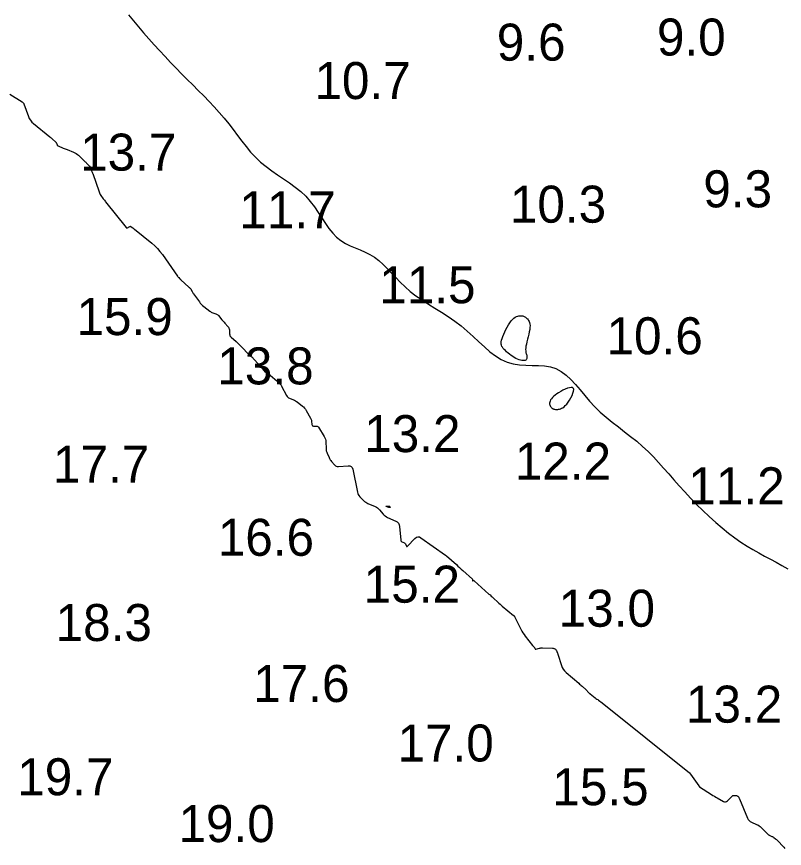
# Model space of a CAD drawing. Extents: x 3040093 to 3056816, y 408076 to 509144.
# Drawn here: x 3044186.9 to 3044290.6, y 435756.3 to 435868.7 of the extents above; entities that cross this region are included whole.
import ezdxf

# ---------------------------------------------------------------- set-up
doc = ezdxf.new("R2010")
doc.units = 0
for name, color, linetype in [('V-CHAN-CONT-EL12-1112', 7, 'Continuous'), ('V-CHAN-CONT-EL15', 7, 'Continuous'), ('V-TOPO-SOUN-0810', 7, 'Continuous')]:
    doc.layers.add(name, color=color, linetype=linetype)

msp = doc.modelspace()

# ---------------------------------------------------------------- linework, layer by layer
at = {"layer": 'V-CHAN-CONT-EL12-1112'}
msp.add_lwpolyline([(3044202, 435868.95), (3044202.67, 435868.14), (3044203.35, 435867.33), (3044204.04, 435866.52), (3044204.75, 435865.71), (3044205.47, 435864.91), (3044206.19, 435864.11), (3044206.93, 435863.32), (3044207.67, 435862.53), (3044208.42, 435861.76), (3044209.17, 435860.99), (3044209.93, 435860.23), (3044210.68, 435859.49), (3044211.43, 435858.74), (3044212.17, 435858), (3044212.89, 435857.26), (3044213.59, 435856.52), (3044214.27, 435855.76), (3044214.92, 435855), (3044215.54, 435854.22), (3044216.13, 435853.44), (3044216.72, 435852.66), (3044217.3, 435851.89), (3044217.89, 435851.14), (3044218.5, 435850.41), (3044219.15, 435849.71), (3044219.84, 435849.06), (3044220.58, 435848.45), (3044221.35, 435847.88), (3044222.15, 435847.33), (3044222.96, 435846.79), (3044223.76, 435846.25), (3044224.54, 435845.68), (3044225.27, 435845.09), (3044225.95, 435844.44), (3044226.56, 435843.75), (3044227.12, 435843.01), (3044227.64, 435842.26), (3044228.13, 435841.51), (3044228.61, 435840.78), (3044229.09, 435840.09), (3044229.59, 435839.46), (3044230.12, 435838.9), (3044230.7, 435838.45), (3044231.32, 435838.07), (3044231.96, 435837.75), (3044232.62, 435837.46), (3044233.29, 435837.18), (3044233.96, 435836.89), (3044234.6, 435836.57), (3044235.23, 435836.19), (3044235.83, 435835.74), (3044236.4, 435835.23), (3044236.96, 435834.67), (3044237.52, 435834.07), (3044238.1, 435833.45), (3044238.71, 435832.82), (3044239.37, 435832.19), (3044240.07, 435831.58), (3044240.84, 435830.99), (3044241.66, 435830.43), (3044242.52, 435829.88), (3044243.4, 435829.33), (3044244.3, 435828.77), (3044245.2, 435828.18), (3044246.09, 435827.57), (3044246.95, 435826.92), (3044247.77, 435826.23), (3044248.56, 435825.51), (3044249.33, 435824.79), (3044250.09, 435824.09), (3044250.84, 435823.44), (3044251.6, 435822.86), (3044252.37, 435822.38), (3044253.16, 435822.02), (3044253.99, 435821.78), (3044254.83, 435821.66), (3044255.68, 435821.61), (3044256.54, 435821.59), (3044257.38, 435821.57), (3044258.21, 435821.51), (3044259, 435821.38), (3044259.75, 435821.15), (3044260.46, 435820.77), (3044261.12, 435820.27), (3044261.76, 435819.67), (3044262.38, 435819), (3044263.01, 435818.27), (3044263.65, 435817.52), (3044264.31, 435816.75), (3044265.01, 435816), (3044265.75, 435815.28), (3044266.54, 435814.59), (3044267.35, 435813.92), (3044268.19, 435813.27), (3044269.02, 435812.63), (3044269.85, 435811.98), (3044270.67, 435811.33), (3044271.45, 435810.65), (3044272.2, 435809.95), (3044272.92, 435809.23), (3044273.62, 435808.49), (3044274.31, 435807.72), (3044274.99, 435806.94), (3044275.69, 435806.14), (3044276.41, 435805.33), (3044277.16, 435804.5), (3044277.95, 435803.66), (3044278.77, 435802.81), (3044279.61, 435801.98), (3044280.47, 435801.16), (3044281.34, 435800.37), (3044282.21, 435799.62), (3044283.08, 435798.92), (3044283.93, 435798.28), (3044284.76, 435797.7), (3044285.58, 435797.17), (3044286.38, 435796.7), (3044287.17, 435796.25), (3044287.96, 435795.83), (3044288.73, 435795.42), (3044289.51, 435795), (3044290.29, 435794.57), (3044291.08, 435794.11)], dxfattribs=at)
for points in [[(3044252.52, 435824.03), (3044252.44, 435824.16), (3044252.38, 435824.3), (3044252.35, 435824.44), (3044252.34, 435824.59), (3044252.37, 435824.77), (3044252.41, 435824.98), (3044252.48, 435825.21), (3044252.58, 435825.49), (3044252.7, 435825.79), (3044252.84, 435826.11), (3044253, 435826.44), (3044253.16, 435826.76), (3044253.34, 435827.07), (3044253.52, 435827.36), (3044253.71, 435827.61), (3044253.89, 435827.81), (3044254.08, 435827.97), (3044254.26, 435828.1), (3044254.43, 435828.19), (3044254.6, 435828.25), (3044254.76, 435828.28), (3044254.9, 435828.3), (3044255.04, 435828.3), (3044255.16, 435828.29), (3044255.27, 435828.27), (3044255.38, 435828.24), (3044255.47, 435828.2), (3044255.56, 435828.15), (3044255.64, 435828.09), (3044255.73, 435828.02), (3044255.81, 435827.94), (3044255.9, 435827.86), (3044255.99, 435827.76), (3044256.07, 435827.65), (3044256.14, 435827.52), (3044256.2, 435827.37), (3044256.24, 435827.18), (3044256.26, 435826.97), (3044256.25, 435826.72), (3044256.22, 435826.44), (3044256.16, 435826.12), (3044256.08, 435825.79), (3044256, 435825.45), (3044255.91, 435825.11), (3044255.83, 435824.78), (3044255.76, 435824.47), (3044255.7, 435824.19), (3044255.67, 435823.95), (3044255.66, 435823.74), (3044255.67, 435823.57), (3044255.69, 435823.42), (3044255.71, 435823.29), (3044255.75, 435823.18), (3044255.78, 435823.07), (3044255.81, 435822.96), (3044255.83, 435822.85), (3044255.84, 435822.74), (3044255.84, 435822.63), (3044255.83, 435822.53), (3044255.8, 435822.44), (3044255.75, 435822.36), (3044255.68, 435822.3), (3044255.58, 435822.25), (3044255.46, 435822.23), (3044255.31, 435822.23), (3044255.15, 435822.26), (3044254.97, 435822.3), (3044254.77, 435822.36), (3044254.56, 435822.44), (3044254.35, 435822.54), (3044254.13, 435822.66), (3044253.91, 435822.79), (3044253.7, 435822.93), (3044253.48, 435823.09), (3044253.28, 435823.25), (3044253.09, 435823.42), (3044252.92, 435823.58), (3044252.76, 435823.74), (3044252.63, 435823.89)], [(3044259.32, 435815.74), (3044259.41, 435815.7), (3044259.49, 435815.67), (3044259.58, 435815.66), (3044259.68, 435815.65), (3044259.78, 435815.64), (3044259.89, 435815.65), (3044260, 435815.65), (3044260.12, 435815.67), (3044260.25, 435815.69), (3044260.39, 435815.73), (3044260.53, 435815.79), (3044260.69, 435815.87), (3044260.85, 435815.99), (3044261.02, 435816.15), (3044261.21, 435816.36), (3044261.4, 435816.61), (3044261.6, 435816.9), (3044261.78, 435817.21), (3044261.94, 435817.52), (3044262.06, 435817.82), (3044262.14, 435818.09), (3044262.16, 435818.32), (3044262.12, 435818.48), (3044262, 435818.58), (3044261.81, 435818.6), (3044261.58, 435818.57), (3044261.3, 435818.49), (3044261, 435818.38), (3044260.7, 435818.23), (3044260.4, 435818.07), (3044260.11, 435817.9), (3044259.86, 435817.73), (3044259.63, 435817.56), (3044259.44, 435817.39), (3044259.28, 435817.23), (3044259.15, 435817.07), (3044259.04, 435816.92), (3044258.97, 435816.77), (3044258.92, 435816.62), (3044258.9, 435816.49), (3044258.9, 435816.36), (3044258.93, 435816.24), (3044258.97, 435816.13), (3044259.02, 435816.03), (3044259.09, 435815.94), (3044259.16, 435815.86), (3044259.24, 435815.79)]]:
    msp.add_lwpolyline(points, close=True, dxfattribs=at)
at = {"layer": 'V-CHAN-CONT-EL15'}
for points in [[(3044185.97, 435858.22), (3044187.62, 435857.2), (3044187.65, 435857.19), (3044187.67, 435857.17), (3044187.69, 435857.15), (3044187.71, 435857.12), (3044187.79, 435857.03), (3044187.81, 435857), (3044187.83, 435856.98), (3044187.84, 435856.95), (3044187.85, 435856.92), (3044188.47, 435855.23), (3044188.59, 435854.95), (3044188.75, 435854.7), (3044188.94, 435854.47), (3044189.17, 435854.26), (3044191.38, 435852.45), (3044191.47, 435852.38), (3044191.55, 435852.31), (3044191.64, 435852.23), (3044191.72, 435852.16), (3044192.13, 435851.81), (3044192.18, 435851.76), (3044192.21, 435851.72), (3044192.24, 435851.67), (3044192.27, 435851.62), (3044192.35, 435851.4), (3044192.38, 435851.34), (3044192.41, 435851.3), (3044192.46, 435851.27), (3044192.51, 435851.24), (3044193.17, 435850.95), (3044193.3, 435850.89), (3044193.43, 435850.84), (3044193.57, 435850.79), (3044193.7, 435850.74), (3044194.57, 435850.4), (3044194.76, 435850.31), (3044194.93, 435850.21), (3044195.1, 435850.1), (3044195.25, 435849.97), (3044196.16, 435849.1), (3044196.22, 435849.04), (3044196.27, 435848.98), (3044196.33, 435848.93), (3044196.39, 435848.87), (3044196.7, 435848.56), (3044196.71, 435848.54), (3044196.73, 435848.53), (3044196.75, 435848.51), (3044196.76, 435848.49), (3044196.83, 435848.42), (3044196.84, 435848.41), (3044196.85, 435848.39), (3044196.86, 435848.37), (3044196.87, 435848.35), (3044196.94, 435848.04), (3044196.95, 435847.99), (3044196.97, 435847.95), (3044196.99, 435847.9), (3044197.01, 435847.86), (3044197.09, 435847.68), (3044197.11, 435847.64), (3044197.13, 435847.59), (3044197.15, 435847.55), (3044197.17, 435847.5), (3044198.02, 435845.03), (3044198.07, 435844.91), (3044198.13, 435844.78), (3044198.19, 435844.67), (3044198.27, 435844.55), (3044198.58, 435844.11), (3044198.66, 435844), (3044198.74, 435843.89), (3044198.83, 435843.78), (3044198.91, 435843.67), (3044201.7, 435840.22), (3044201.7, 435840.21), (3044201.71, 435840.21), (3044201.72, 435840.19), (3044201.73, 435840.18), (3044201.73, 435840.18), (3044201.74, 435840.17), (3044201.74, 435840.17), (3044201.77, 435840.15), (3044201.77, 435840.15), (3044201.78, 435840.15), (3044201.79, 435840.15), (3044201.79, 435840.15), (3044202.17, 435840.35), (3044202.22, 435840.37), (3044202.28, 435840.38), (3044202.33, 435840.36), (3044202.38, 435840.33), (3044202.59, 435840.17), (3044202.64, 435840.13), (3044202.69, 435840.09), (3044202.74, 435840.05), (3044202.79, 435840.01), (3044205.14, 435838.08), (3044205.54, 435837.73), (3044205.91, 435837.36), (3044206.25, 435836.96), (3044206.57, 435836.55), (3044208.64, 435833.64), (3044208.65, 435833.62), (3044208.66, 435833.61), (3044208.67, 435833.59), (3044208.68, 435833.58), (3044208.73, 435833.5), (3044208.73, 435833.49), (3044208.73, 435833.49), (3044208.74, 435833.49), (3044208.74, 435833.48), (3044208.76, 435833.47), (3044208.77, 435833.47), (3044208.77, 435833.47), (3044208.78, 435833.46), (3044208.78, 435833.46), (3044208.95, 435833.28), (3044208.98, 435833.25), (3044209.01, 435833.22), (3044209.04, 435833.19), (3044209.07, 435833.16), (3044210.17, 435832.17), (3044210.24, 435832.1), (3044210.3, 435832.03), (3044210.36, 435831.96), (3044210.41, 435831.88), (3044210.6, 435831.56), (3044210.65, 435831.48), (3044210.7, 435831.4), (3044210.75, 435831.32), (3044210.8, 435831.24), (3044211.57, 435830.16), (3044211.7, 435829.99), (3044211.84, 435829.83), (3044212, 435829.69), (3044212.16, 435829.55), (3044213.01, 435828.91), (3044213.09, 435828.85), (3044213.19, 435828.79), (3044213.28, 435828.75), (3044213.38, 435828.71), (3044213.79, 435828.57), (3044213.89, 435828.53), (3044213.98, 435828.47), (3044214.07, 435828.41), (3044214.14, 435828.33), (3044214.63, 435827.74), (3044214.73, 435827.63), (3044214.82, 435827.52), (3044214.92, 435827.41), (3044215.02, 435827.3), (3044215.43, 435826.86), (3044215.51, 435826.76), (3044215.57, 435826.64), (3044215.61, 435826.52), (3044215.63, 435826.39), (3044215.65, 435825.85), (3044215.67, 435825.72), (3044215.71, 435825.6), (3044215.77, 435825.5), (3044215.86, 435825.4), (3044216.53, 435824.81), (3044216.67, 435824.68), (3044216.81, 435824.55), (3044216.95, 435824.42), (3044217.09, 435824.28), (3044218.43, 435822.9), (3044218.44, 435822.89), (3044218.46, 435822.87), (3044218.48, 435822.86), (3044218.5, 435822.84), (3044218.58, 435822.8), (3044218.6, 435822.78), (3044218.62, 435822.77), (3044218.64, 435822.75), (3044218.65, 435822.74), (3044220.18, 435821.02), (3044220.2, 435820.99), (3044220.23, 435820.96), (3044220.25, 435820.94), (3044220.28, 435820.91), (3044220.37, 435820.79), (3044220.39, 435820.76), (3044220.42, 435820.74), (3044220.45, 435820.72), (3044220.48, 435820.7), (3044220.89, 435820.45), (3044220.96, 435820.41), (3044221.04, 435820.35), (3044221.11, 435820.3), (3044221.18, 435820.24), (3044222.05, 435819.49), (3044222.11, 435819.44), (3044222.17, 435819.38), (3044222.23, 435819.33), (3044222.29, 435819.27), (3044222.51, 435819.03), (3044222.56, 435818.97), (3044222.61, 435818.9), (3044222.65, 435818.84), (3044222.69, 435818.77), (3044223.34, 435817.52), (3044223.42, 435817.4), (3044223.52, 435817.3), (3044223.63, 435817.21), (3044223.76, 435817.15), (3044224.3, 435816.94), (3044224.44, 435816.88), (3044224.57, 435816.81), (3044224.69, 435816.73), (3044224.81, 435816.65), (3044225.51, 435816.1), (3044225.66, 435815.97), (3044225.8, 435815.83), (3044225.92, 435815.67), (3044226.02, 435815.51), (3044226.59, 435814.48), (3044226.64, 435814.38), (3044226.68, 435814.28), (3044226.71, 435814.17), (3044226.73, 435814.06), (3044226.78, 435813.59), (3044226.8, 435813.51), (3044226.84, 435813.44), (3044226.91, 435813.41), (3044226.99, 435813.39), (3044227.39, 435813.39), (3044227.48, 435813.38), (3044227.56, 435813.35), (3044227.63, 435813.3), (3044227.69, 435813.22), (3044228.45, 435811.98), (3044228.55, 435811.81), (3044228.61, 435811.62), (3044228.66, 435811.43), (3044228.67, 435811.24), (3044228.69, 435810.35), (3044228.71, 435810.19), (3044228.73, 435810.03), (3044228.78, 435809.88), (3044228.84, 435809.73), (3044229.11, 435809.13), (3044229.18, 435808.99), (3044229.25, 435808.85), (3044229.34, 435808.73), (3044229.44, 435808.61), (3044229.85, 435808.14), (3044229.95, 435808.03), (3044230.08, 435807.97), (3044230.21, 435807.93), (3044230.36, 435807.93), (3044231.66, 435808.04), (3044231.9, 435808.03), (3044232.09, 435807.94), (3044232.22, 435807.79), (3044232.3, 435807.56), (3044232.92, 435804.47), (3044232.97, 435804.3), (3044233.04, 435804.14), (3044233.13, 435803.99), (3044233.25, 435803.85), (3044233.77, 435803.34), (3044233.9, 435803.22), (3044234.05, 435803.11), (3044234.2, 435803.02), (3044234.36, 435802.94), (3044235.32, 435802.52), (3044235.49, 435802.44), (3044235.65, 435802.34), (3044235.79, 435802.22), (3044235.92, 435802.09), (3044236.42, 435801.51), (3044236.55, 435801.37), (3044236.69, 435801.25), (3044236.85, 435801.15), (3044237.01, 435801.06), (3044238.1, 435800.56), (3044238.32, 435800.43), (3044238.48, 435800.26), (3044238.58, 435800.05), (3044238.63, 435799.81), (3044238.78, 435797.97), (3044238.8, 435797.9), (3044238.83, 435797.84), (3044238.87, 435797.8), (3044238.93, 435797.76), (3044239.21, 435797.65), (3044239.27, 435797.62), (3044239.33, 435797.58), (3044239.37, 435797.52), (3044239.41, 435797.46), (3044239.55, 435797.18), (3044239.58, 435797.13), (3044239.62, 435797.1), (3044239.67, 435797.11), (3044239.72, 435797.15), (3044240.71, 435798.22), (3044240.9, 435798.37), (3044241.09, 435798.43), (3044241.3, 435798.41), (3044241.51, 435798.3), (3044244.83, 435795.95), (3044244.84, 435795.94), (3044244.84, 435795.94), (3044244.85, 435795.93), (3044244.85, 435795.93), (3044244.86, 435795.91), (3044244.87, 435795.91), (3044244.87, 435795.9), (3044244.88, 435795.9), (3044244.88, 435795.9), (3044244.94, 435795.88), (3044244.95, 435795.87), (3044244.96, 435795.87), (3044244.97, 435795.86), (3044244.97, 435795.86), (3044246.3, 435794.68), (3044246.52, 435794.48), (3044246.74, 435794.28), (3044246.96, 435794.08), (3044247.18, 435793.88), (3044248.47, 435792.7), (3044248.48, 435792.69), (3044248.49, 435792.67), (3044248.49, 435792.65), (3044248.49, 435792.63), (3044248.46, 435792.54), (3044248.45, 435792.52), (3044248.46, 435792.51), (3044248.47, 435792.5), (3044248.49, 435792.5), (3044248.6, 435792.52), (3044248.63, 435792.53), (3044248.65, 435792.52), (3044248.68, 435792.51), (3044248.7, 435792.5), (3044250.7, 435790.7), (3044250.85, 435790.57), (3044251, 435790.43), (3044251.15, 435790.3), (3044251.3, 435790.16), (3044251.9, 435789.61), (3044252.05, 435789.48), (3044252.2, 435789.34), (3044252.35, 435789.21), (3044252.5, 435789.08), (3044254.04, 435787.82), (3044254.06, 435787.81), (3044254.07, 435787.79), (3044254.08, 435787.78), (3044254.09, 435787.77), (3044254.13, 435787.71), (3044254.14, 435787.7), (3044254.15, 435787.69), (3044254.15, 435787.67), (3044254.16, 435787.66), (3044255.02, 435785.94), (3044255.15, 435785.7), (3044255.3, 435785.47), (3044255.45, 435785.24), (3044255.61, 435785.01), (3044256.59, 435783.75), (3044256.61, 435783.73), (3044256.63, 435783.7), (3044256.65, 435783.68), (3044256.68, 435783.66), (3044256.76, 435783.57), (3044256.79, 435783.55), (3044256.81, 435783.52), (3044256.82, 435783.49), (3044256.84, 435783.47), (3044256.94, 435783.3), (3044256.96, 435783.27), (3044256.99, 435783.25), (3044257.02, 435783.24), (3044257.06, 435783.25), (3044257.54, 435783.38), (3044257.64, 435783.4), (3044257.73, 435783.41), (3044257.83, 435783.42), (3044257.92, 435783.42), (3044259.3, 435783.39), (3044259.35, 435783.39), (3044259.4, 435783.38), (3044259.45, 435783.36), (3044259.5, 435783.34), (3044259.68, 435783.23), (3044259.73, 435783.2), (3044259.76, 435783.17), (3044259.79, 435783.13), (3044259.82, 435783.08), (3044259.93, 435782.81), (3044259.95, 435782.75), (3044259.98, 435782.69), (3044260, 435782.63), (3044260.02, 435782.56), (3044260.5, 435781.04), (3044260.61, 435780.77), (3044260.74, 435780.53), (3044260.91, 435780.31), (3044261.12, 435780.11), (3044262.85, 435778.64), (3044262.96, 435778.54), (3044263.07, 435778.45), (3044263.18, 435778.35), (3044263.29, 435778.25), (3044263.83, 435777.74), (3044263.88, 435777.69), (3044263.92, 435777.65), (3044263.97, 435777.6), (3044264.01, 435777.55), (3044264.19, 435777.37), (3044264.24, 435777.32), (3044264.28, 435777.28), (3044264.33, 435777.24), (3044264.38, 435777.2), (3044265.04, 435776.69), (3044265.16, 435776.6), (3044265.28, 435776.51), (3044265.4, 435776.43), (3044265.52, 435776.34), (3044265.99, 435776), (3044277.8, 435766.52)], [(3044277.8, 435766.52), (3044277.92, 435766.36), (3044279.05, 435764.79), (3044279.05, 435764.78), (3044279.06, 435764.77), (3044279.07, 435764.77), (3044279.07, 435764.76), (3044279.11, 435764.73), (3044279.12, 435764.72), (3044279.13, 435764.71), (3044279.14, 435764.68), (3044279.15, 435764.68), (3044279.15, 435764.67), (3044279.16, 435764.67), (3044279.17, 435764.67), (3044280.78, 435763.62), (3044280.97, 435763.5), (3044281.16, 435763.39), (3044281.35, 435763.27), (3044281.54, 435763.16), (3044282.4, 435762.68), (3044282.55, 435762.62), (3044282.68, 435762.61), (3044282.81, 435762.66), (3044282.94, 435762.76), (3044283.57, 435763.4), (3044283.61, 435763.44), (3044283.66, 435763.47), (3044283.71, 435763.49), (3044283.77, 435763.49), (3044284.1, 435763.5), (3044284.12, 435763.5), (3044284.14, 435763.5), (3044284.15, 435763.49), (3044284.17, 435763.48), (3044284.24, 435763.43), (3044284.24, 435763.43), (3044284.25, 435763.42), (3044284.26, 435763.42), (3044284.27, 435763.41), (3044284.32, 435763.4), (3044284.33, 435763.39), (3044284.33, 435763.39), (3044284.34, 435763.38), (3044284.35, 435763.37), (3044284.42, 435763.3), (3044284.43, 435763.28), (3044284.45, 435763.26), (3044284.46, 435763.25), (3044284.46, 435763.23), (3044284.51, 435763.11), (3044284.52, 435763.09), (3044284.53, 435763.06), (3044284.54, 435763.04), (3044284.55, 435763.01), (3044285.66, 435760.4), (3044285.75, 435760.23), (3044285.86, 435760.09), (3044286, 435759.98), (3044286.17, 435759.89), (3044286.88, 435759.58), (3044287.05, 435759.5), (3044287.21, 435759.4), (3044287.37, 435759.29), (3044287.51, 435759.16), (3044288.44, 435758.23), (3044288.5, 435758.18), (3044288.55, 435758.14), (3044288.62, 435758.1), (3044288.68, 435758.07), (3044288.95, 435757.95), (3044289.01, 435757.92), (3044289.08, 435757.88), (3044289.14, 435757.84), (3044289.2, 435757.8), (3044289.43, 435757.63), (3044289.48, 435757.58), (3044289.54, 435757.54), (3044289.59, 435757.49), (3044289.64, 435757.44), (3044290.53, 435756.51), (3044290.69, 435756.34)]]:
    msp.add_lwpolyline(points, dxfattribs=at)
msp.add_lwpolyline([(3044237.36, 435802.4), (3044237.35, 435802.39), (3044237.34, 435802.38), (3044237.32, 435802.38), (3044237.17, 435802.41), (3044237.14, 435802.42), (3044237.11, 435802.42), (3044237.08, 435802.43), (3044237.04, 435802.45), (3044236.81, 435802.54), (3044236.77, 435802.55), (3044236.76, 435802.57), (3044236.77, 435802.57), (3044236.81, 435802.58), (3044237.22, 435802.57), (3044237.25, 435802.57), (3044237.27, 435802.56), (3044237.29, 435802.54), (3044237.3, 435802.52), (3044237.35, 435802.42)], close=True, dxfattribs=at)

# ---------------------------------------------------------------- texts
at = {"layer": 'V-TOPO-SOUN-0810'}
for s, p in [('9.0', (3044273.4, 435863.45)), ('9.6', (3044251.76, 435862.76)), ('10.7 ', (3044227.12, 435857.57)), ('13.7 ', (3044195.46, 435847.9)), ('9.3', (3044279.67, 435842.94)), ('10.3 ', (3044253.53, 435840.87)), ('11.7 ', (3044216.98, 435840.12)), ('11.5 ', (3044235.88, 435829.98)), ('15.9 ', (3044194.97, 435825.68)), ('10.6 ', (3044266.59, 435823.09)), ('13.8 ', (3044214, 435819.02)), ('13.2 ', (3044233.85, 435809.87)), ('12.2 ', (3044254.19, 435806.16)), ('17.7 ', (3044191.79, 435805.74)), ('11.2 ', (3044277.65, 435802.82)), ('16.6 ', (3044214.06, 435795.86)), ('15.2 ', (3044233.78, 435789.53)), ('13.0 ', (3044260.13, 435786.28)), ('18.3 ', (3044192.15, 435784.35)), ('17.6 ', (3044218.85, 435776.11)), ('13.2 ', (3044277.32, 435773.32)), ('17.0 ', (3044238.34, 435768.07)), ('19.7 ', (3044186.96, 435763.51)), ('15.5 ', (3044259.27, 435762.17)), ('19.0 ', (3044208.75, 435757.18))]:
    msp.add_text(s, height=5, dxfattribs=at).set_placement(p)

doc.saveas('drawing.dxf')
